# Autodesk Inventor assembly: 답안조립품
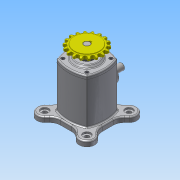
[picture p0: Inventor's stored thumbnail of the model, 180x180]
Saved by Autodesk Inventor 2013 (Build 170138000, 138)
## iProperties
Created: 2016-05
Part Number: 답안조립품
Document SubType Name: Assembly
Designer: Administrator
Author: Administrator
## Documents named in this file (11)
- C:\Users\Administrator\Desktop\460507v1008\답안조립품.iam
- C:\Users\Administrator\Desktop\460507v1008\1-본체.ipt
- C:\Users\Administrator\Desktop\460507v1008\편심축.ipt
- C:\Users\Administrator\Desktop\460507v1008\베어링-6203.ipt
- C:\Users\Administrator\Desktop\460507v1008\키5x5.ipt
- C:\Users\Administrator\Desktop\460507v1008\스프로킷.ipt
- C:\Users\Administrator\Desktop\460507v1008\커버.ipt
- C:\Users\Administrator\Desktop\460507v1008\오일실.ipt
- C:\Users\Administrator\Desktop\460507v1008\M4x0.7x12.ipt
- C:\Users\Administrator\Desktop\460507v1008\부시.ipt
- C:\Users\Administrator\Desktop\460507v1008\슬라이더.ipt
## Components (9 placed, 2 different names)
1. 1-본체:1
2. M4x0.7x12:1
3. M4x0.7x12:3
4. M4x0.7x12:4
5. M4x0.7x12:5
6. M4x0.7x12:2
7. M4x0.7x12:6
8. M4x0.7x12:7
9. M4x0.7x12:8
